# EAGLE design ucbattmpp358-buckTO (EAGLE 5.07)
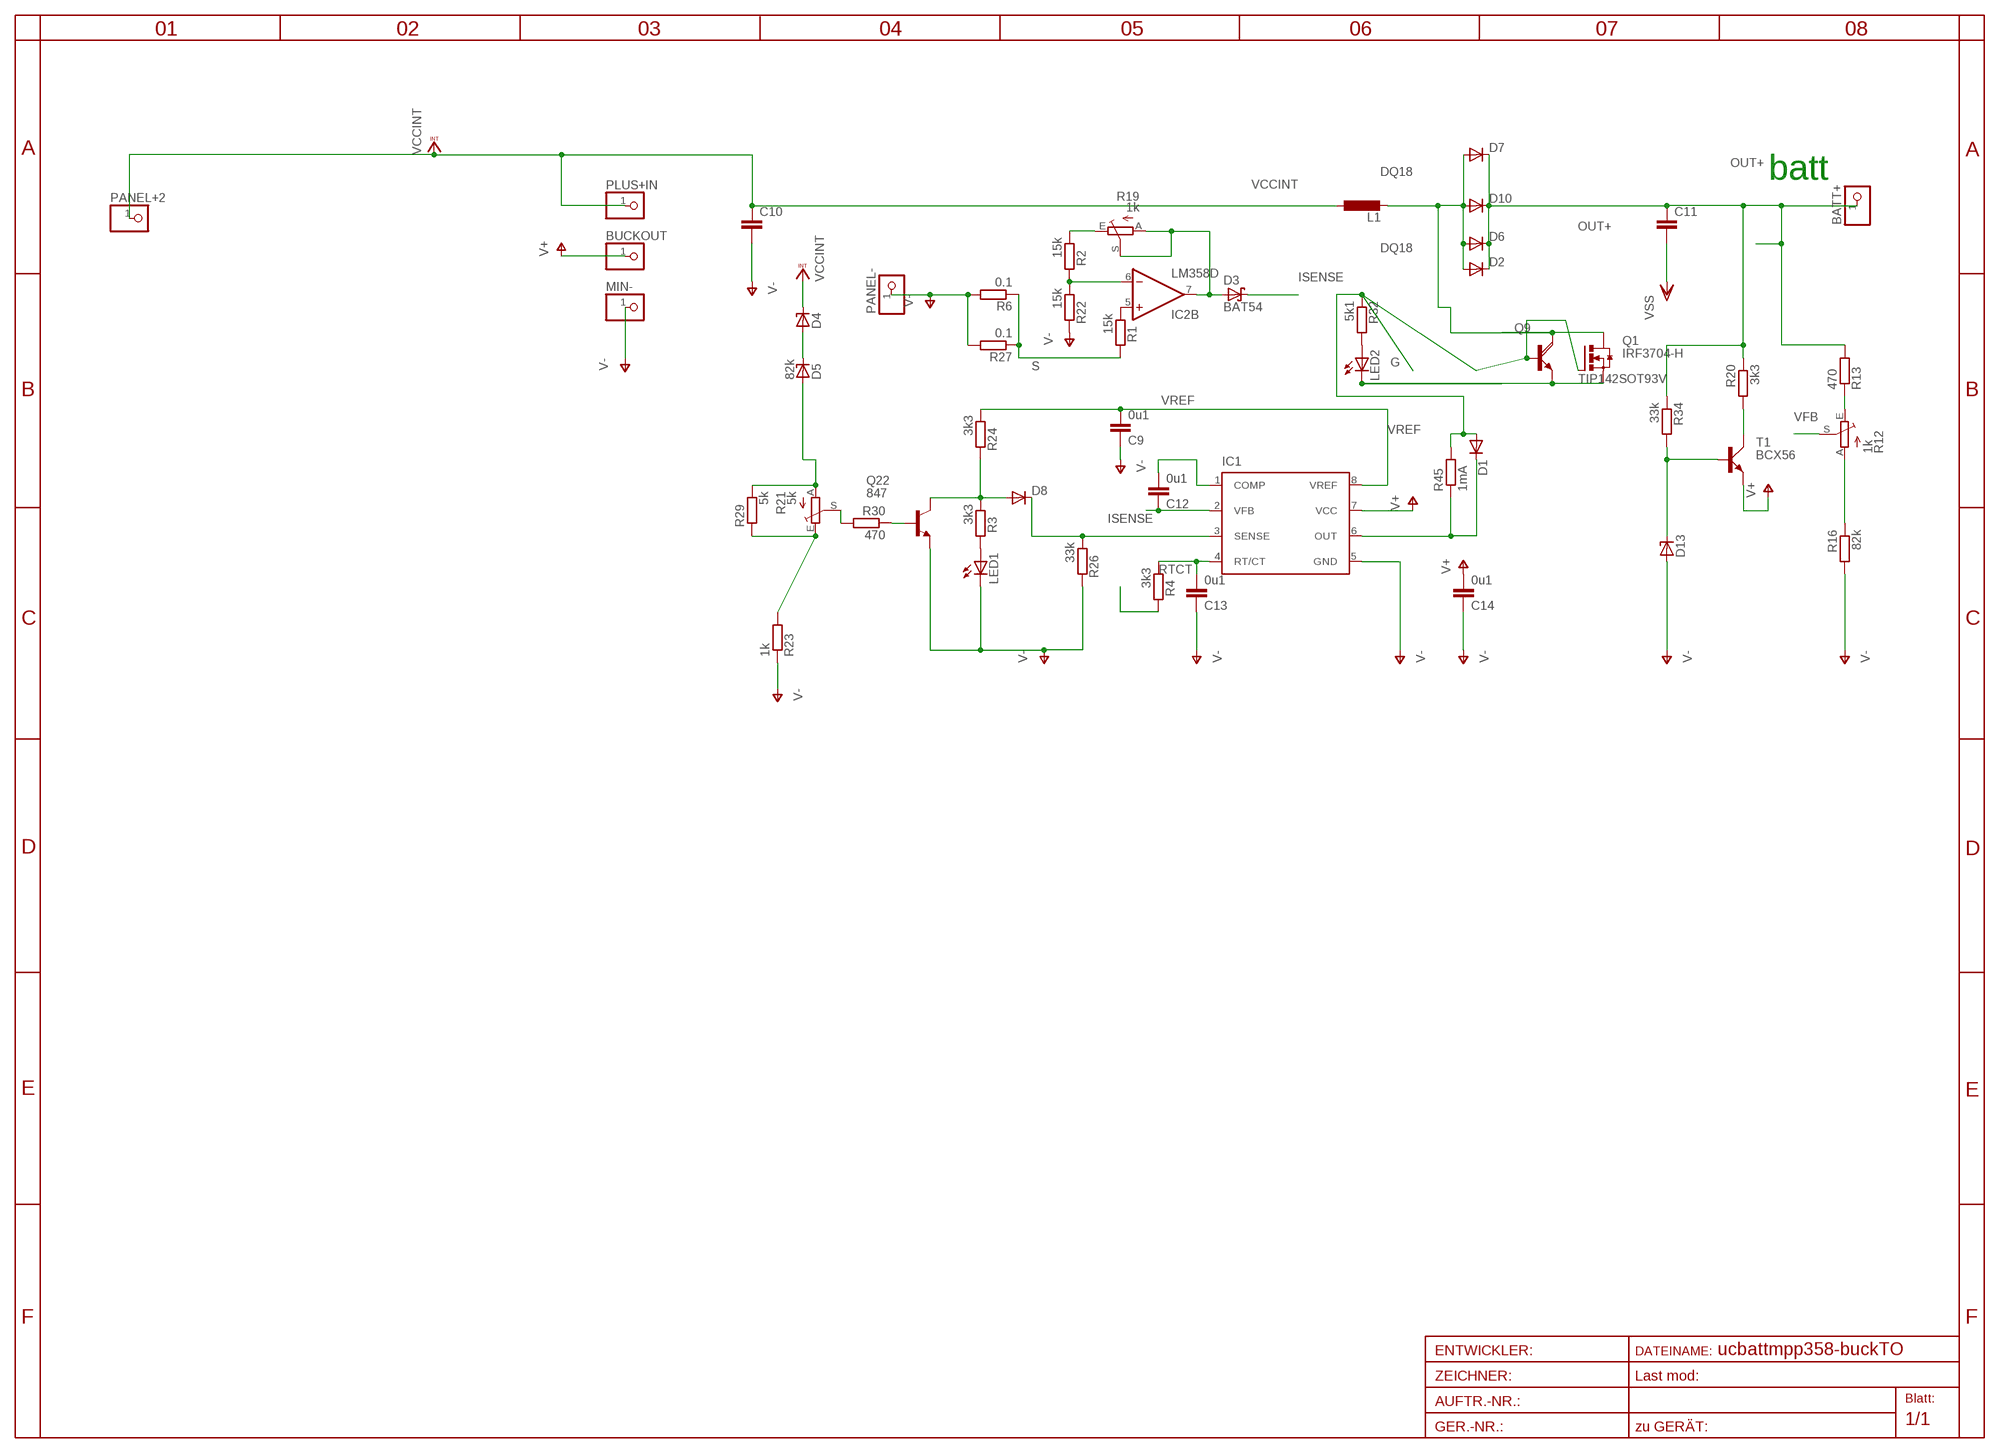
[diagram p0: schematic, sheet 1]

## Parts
BATT+  PINHD-1X12MM3  [1X2MM3]
BUCKOUT  PINHD-1X11MM0  [1X1MM0]
C9  0u1  C-EUC1206  [C1206]
C10  C-EU075-052X106  [C075-052X106]
C11  C-EU075-052X106  [C075-052X106]
C12  0u1  C-EUC0805  [C0805]
C13  0u1  C-EUC1206  [C1206]
C14  0u1  C-EUC1206  [C1206]
D1  DIODE-MINIMELF  [MINIMELF]
D2  DIODE-SMC  [SMC]
D3  BAT54  [SOT23]
D4  ZENER-DIODESOD80C  [SOD80C]
D5  82k  ZENER-DIODESOD80C  [SOD80C]
D6  DIODE-SMC  [SMC]
D7  DIODE-SMC  [SMC]
D8  DIODE-MINIMELF  [MINIMELF]
D10  DIODE-SMC  [SMC]
D13  ZENER-DIODESOD80C  [SOD80C]
IC1  UC1843D8  [SO-08]
IC2  LM358D  [SO08]
L1  L-EUOPEN6  [OPEN6_3]
LED1  LEDCHIPLED_1206  [CHIPLED_1206]
LED2  LEDCHIPLED_1206  [CHIPLED_1206]
MIN-  PINHD-1X11MM0  [1X1MM0]
PANEL+2  PINHD-1X12MM3  [1X2MM3]
PANEL-  PINHD-1X12MM3  [1X2MM3]
PLUS+IN  PINHD-1X11MM0  [1X1MM0]
Q1  IRF3704-H  [TO220BH]
Q9  TIP142SOT93V  [SOT93V]
Q22  847  BC847ASMD  [SOT23]
R1  15k  R-EU_R0805  [R0805]
R2  15k  R-EU_R0805  [R0805]
R3  3k3  R-EU_R0805  [R0805]
R4  3k3  R-EU_R0805  [R0805]
R6  0.1  R-EU_0207/10  [0207/10]
R12  1k  TRIM_EU-S64W  [S64W]
R13  470  R-EU_R0805  [R0805]
R16  82k  R-EU_R0805  [R0805]
R19  1k  TRIM_EU-S64W  [S64W]
R20  3k3  R-EU_R0805  [R0805]
R21  5k  TRIM_EU-S64W  [S64W]
R22  15k  R-EU_R0805  [R0805]
R23  1k  R-EU_R0805  [R0805]
R24  3k3  R-EU_R0805  [R0805]
R26  33k  R-EU_R0805  [R0805]
R27  0.1  R-EU_R3216  [R3216]
R29  5k  R-EU_R0805  [R0805]
R30  470  R-EU_R0805  [R0805]
R32  5k1  R-EU_R0805  [R0805]
R34  33k  R-EU_R0805  [R0805]
R45  1mA  R-EU_R0805  [R0805]
T1  BCX56  [SOT223]

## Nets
DQ18: D2.A D6.A D7.A D10.A L1.2 Q1.D Q9.C
G: D1.A Q1.G Q9.B R32.1 R45.2
ISENSE: D3.3(C) D8.C IC1.3(SENSE) R26.1
N$1: IC2.5(B:+IN) R1.1
N$2: R2.1 R19.E
N$3: Q22.1(B) R30.1
N$4: LED1.A R3.2
N$5: LED2.A R32.2
N$18: C12.2 IC1.1(COMP)
N$21: R12.A R16.1
N$22: D3.1(A) IC2.7(B:OUT) R19.A R19.S
N$23: R20.2 T1.2(C)
N$25: D1.C IC1.6(OUT) R45.1
N$26: D13.C R34.2 T1.1(B)
N$27: IC2.6(B:-IN) R2.2 R22.1
N$30: D4.A D5.C
N$32: D5.A R21.A R29.1
N$34: R21.E R23.2 R29.2
N$37: R12.E R13.1
N$71: D8.A Q22.3(C) R3.1 R24.2
OUT+: BATT+.1 C11.1 D2.C D6.C D7.C D10.C R13.2 R20.1 R34.1
PRB1: R21.S R30.2
RTCT: C13.2 IC1.4(RT/CT) R4.1
S: LED2.C Q1.S Q9.E R1.2 R6.1 R27.1
V+: BUCKOUT.1 C14.2 IC1.7(VCC) T1.3(E)
V-: C9.1 C10.2 C11.2 C13.1 C14.1 D13.A IC1.5(GND) LED1.C MIN-.1 PANEL-.1 Q22.2(E) R6.2 R16.2 R22.2 R23.1 R26.2 R27.2 ; supply symbol labelled VSS
VCCINT: C10.1 D4.C L1.1 PANEL+2.1 PLUS+IN.1
VFB: C12.1 IC1.2(VFB) R12.S
VREF: C9.2 IC1.8(VREF) R4.2 R24.1
Unconnected: IC2.1(A:OUT) IC2.2(A:-IN) IC2.3(A:+IN)

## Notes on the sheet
- batt

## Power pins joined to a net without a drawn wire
V+: IC2.8(P:V+)
V-: IC2.4(P:V-)

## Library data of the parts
BATT+ BUCKOUT MIN- PANEL+2 PANEL- PLUS+IN = pinhead:PINHD-1X1: PIN HEADER
C9-C14 = rcl:C-EU: CAPACITOR, European symbol
D1 D2 D6-D8 D10 = diode:DIODE-: DIODE
D3 = diode:BAT54: Schottky Diodes
D4 D5 D13 = diode:ZENER-DIODE: Z-Diode
IC1 = texas:UC1843D8: PULSE WIDTH MODULATOR
IC2 = linear:LM358: OP AMP also LM158; LM258; LM2904 Source: http://cache.national.com/ds/LM/LM158.pdf
L1 = rcl:L-EU: INDUCTOR, European symbol
LED1 LED2 = led:LED: LED
Q1 = transistor-power:IRF3704: SMPS MOSFET HEXFET® Power MOSFET Source: http://www.irf.com/product-info/datasheets/data/irf3704.pdf
Q9 = transistor-power:TIP142: NPN DARLINGTON TRANSISTOR
Q22 = transistor-npn:BC847*: NPN Transistor
R1-R4 R6 R13 R16 R20 R22-R24 R26 R27 R29 R30 R34 = rcl:R-EU_: RESISTOR, European symbol
R12 R19 R21 = pot:TRIM_EU-: POTENTIOMETER
R32 R45 = rcl-2:R-EU_: RESISTOR, European symbol
T1 = transistor-power:BCX56

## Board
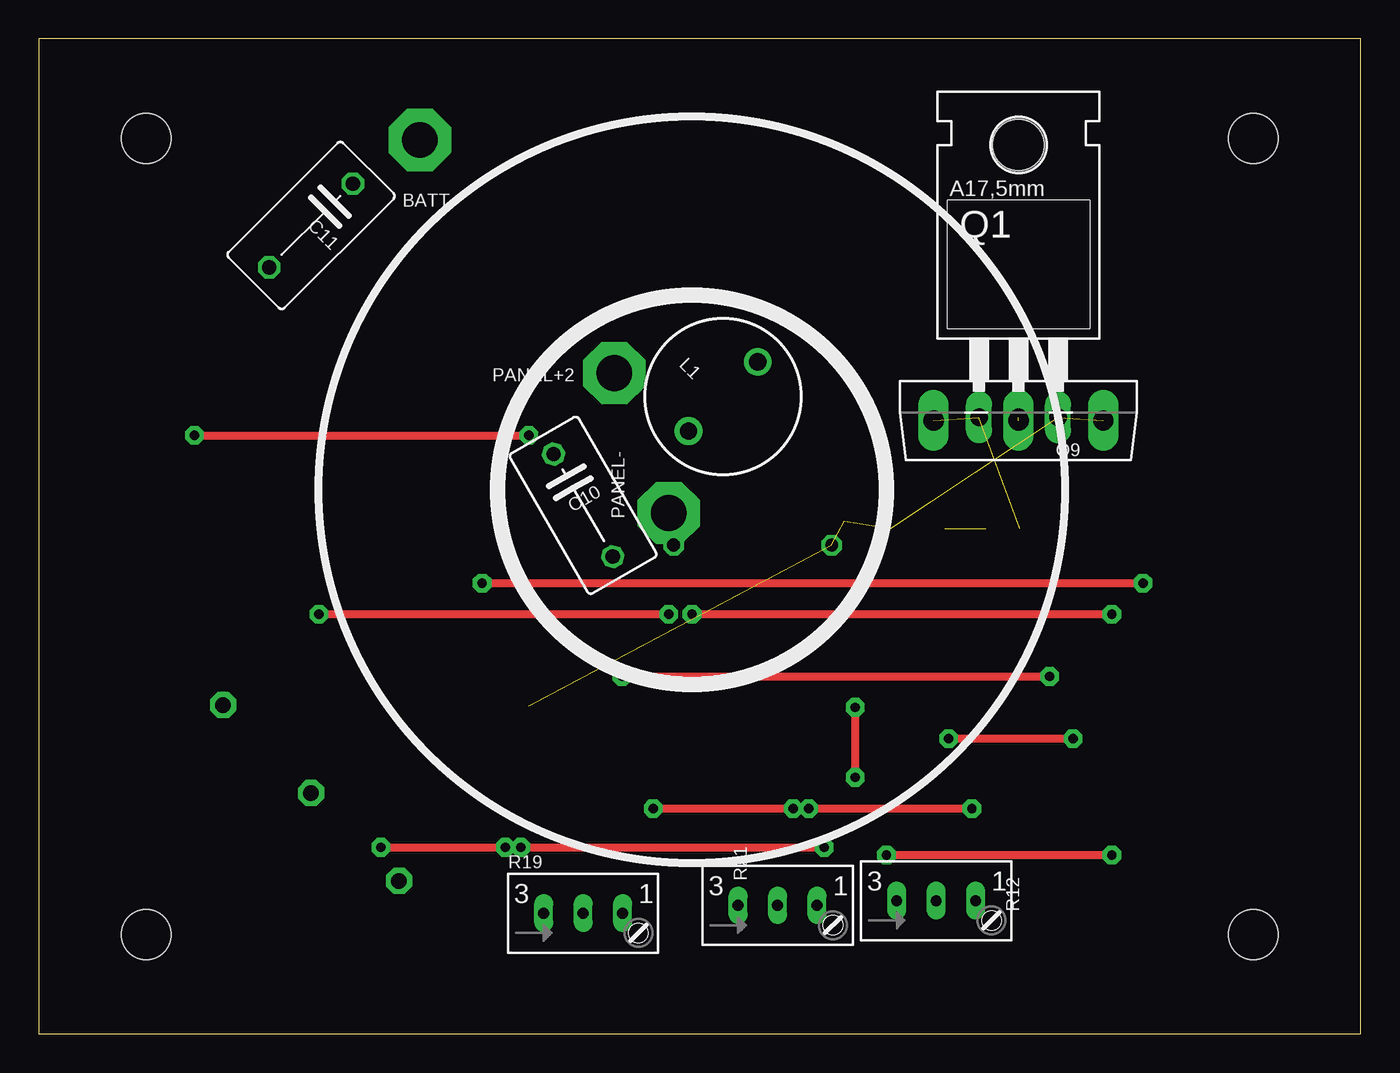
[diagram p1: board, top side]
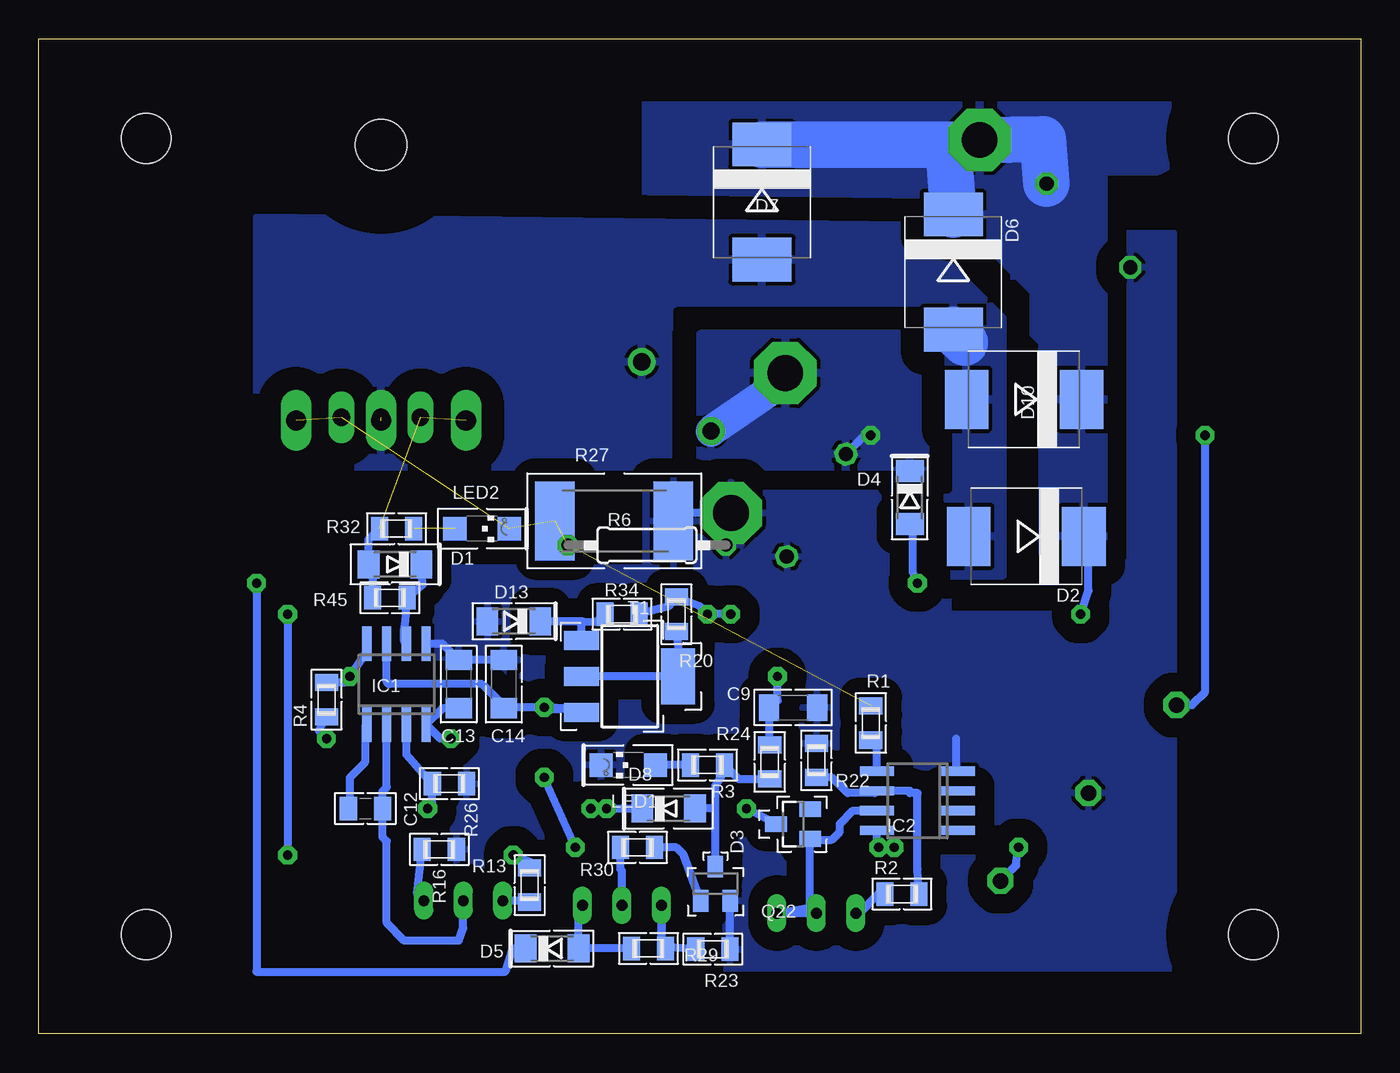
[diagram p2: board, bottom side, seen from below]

Size 85 x 64 mm. Coordinates in mm from the lower left corner, seen from the top.
Outline: 0,0 85,0 85,64 0,64 0,0
Copper layers (1*16): Top 0.035mm / dielectric 1.5mm / Bottom 0.035mm
Design rules "default *": minimum track width 10mil, minimum drill 24mil, track to track 8mil, track to pad 8mil, pad to pad 8mil, via to via 8mil, smd to smd 8mil, copper to edge 4mm, drill to drill 8mil, minimum pad ring 10mil, minimum via ring 8mil, stop-mask expansion 4mil, vias tented up to drill 0mil, thermal gap 10mil
Holes 3.2 mm at 6.9,57.6 6.9,6.4 78.1,6.4 78.1,57.6

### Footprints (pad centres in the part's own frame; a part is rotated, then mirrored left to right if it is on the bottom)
1X2MM3 = drill 2.3 pad 4 octagon: 1 0,0
1X1MM0 = drill 1 pad 1.676 octagon: 1 0,0
C1206 = smd 1.3 x 1.7: 1 -1.55,0; 2 1.55,0
C075-052X106 = drill 0.914 octagon: 1 -3.81,0; 2 3.81,0
C0805 = smd 1.1 x 1.5: 1 -1.1,0; 2 1.1,0
MINIMELF = smd 1.4 x 1.8: A 1.7,0; C -1.7,0
SMC = smd 2.8 x 3.8: A 3.7,0; C -3.7,0
SOT23 = smd 1 x 1.4: 1 -0.95,-1.1; 2 0.95,-1.1; 3 0,1.1
SOD80C = smd 1.4 x 1.8: A 1.7,0; C -1.7,0
SO-08 = smd 0.6 x 2.2: 1 -1.905,-2.6; 2 -0.635,-2.6; 3 0.635,-2.6; 4 1.905,-2.6; 5 1.905,2.6; 6 0.635,2.6; 7 -0.635,2.6; 8 -1.905,2.6
SO08 = smd 0.6 x 2.2: 1 -1.905,-2.6; 2 -0.635,-2.6; 3 0.635,-2.6; 4 1.905,-2.6; 5 1.905,2.6; 6 0.635,2.6; 7 -0.635,2.6; 8 -1.905,2.6
OPEN6_3 = drill 1.1 pad 1.778 round: 1 -3.15,0; 2 3.15,0
CHIPLED_1206 = smd 1.5 x 1.5: A 0,-1.75; C 0,1.75
TO220BH = drill 1.118 long: D 0,-6.35; G -2.54,-6.35; S 2.54,-6.35 | hole 3.302: 0,11.176
SOT93V = drill 1.3 pad 1.676 long: B -5.461,-2.54; C 0,-2.54; E 5.461,-2.54
R0805 = smd 1.1 x 1.5: 1 -1.1,0; 2 1.1,0
0207/10 = drill 0.813 octagon: 1 -5.08,0; 2 5.08,0
S64W = drill 0.7 long: A 2.54,1.27; E -2.54,1.27; S 0,1.27
R3216 = smd 2.54 x 5.08: 1 -3.81,0; 2 3.81,0
SOT223 = smd 1.219 x 2.235: 1 -2.311,-3.099; 2 0,-3.099; 3 2.311,-3.099 | smd 3.6 x 2.2: 4 0,3.099

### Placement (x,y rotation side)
BATT+  24.5,57.5 0 top
BUCKOUT  23.16,9.84 90 top
C9  36.5,21 180 bottom
C10  35,34 300 top
C11  17.5,52 225 top
C12  64,14.5 180 bottom
C13  58,22.5 270 bottom
C14  55.1,22.5 270 bottom
D1  62.1,30.2 180 bottom
D2  21.5,32 180 bottom
D3  36.5,13.5 90 bottom
D4  29,34.5 270 bottom
D5  52,5.5 0 bottom
D6  26.2,49 270 bottom
D7  38.5,53.5 270 bottom
D8  44.5,14.5 0 bottom
D10  21.65,40.81 180 bottom
D13  54.46,26.55 180 bottom
IC1  62,22.5 0 bottom
IC2  28.5,15 90 bottom
L1  44,41 45 top
LED1  47.1,17.3 90 bottom
LED2  56.5,32.5 270 bottom
MIN-  17.5,15.5 315.7 top
PANEL+2  37,42.5 0 top
PANEL-  40.5,33.5 90 top
PLUS+IN  11.84,21.16 90 top
Q1  63,46 0 top
Q9  63,42 0 top
Q22  41.49,9.66 0 bottom
R1  31.5,20 90 bottom
R2  29.5,9 0 bottom
R3  42,17.3 180 bottom
R4  66.5,21.5 90 bottom
R6  45.9,31.45 0 bottom
R12  57.7,7.3 0 top
R13  53.44,9.58 90 bottom
R16  59.25,11.88 0 bottom
R19  35,6.5 0 top
R20  44,27 270 bottom
R21  47.51,7 0 top
R22  35,17.6 90 bottom
R23  41.66,5.46 180 bottom
R24  38,17.5 270 bottom
R26  58.6,16.1 0 bottom
R27  48,33 0 bottom
R29  45.8,5.5 0 bottom
R30  46.5,12 180 bottom
R32  62,32.5 0 bottom
R34  47.5,27 180 bottom
R45  62.43,28.05 180 bottom
T1  47,23 270 bottom

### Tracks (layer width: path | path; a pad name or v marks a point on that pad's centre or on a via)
DQ18  (1 unrouted)
  Bottom 3: D6.A 25.8,44.8 25.45,44.45
  pour Bottom (isolate 1.5, rank 2): 29,52 71,52.5 71,36.5 44.5,36.5 44.5,45.5 27.5,45.5 27.5,29.5 23,29.5 23,46
G  (2 unrouted)
  Bottom 0.5: R45.2 63.53,29.43 D1.A 63.8,31.8 R32.1
ISENSE  (via drill 0.6 pad 1.2)
  Top 0.5: v49.5,14.5 v60,14.5 | v39.5,14.5 v48.5,14.5
  Bottom 0.5: IC1.3 61.37,17.96 R26.1 59.7,14.8 v60,14.5 | v49.5,14.5 v48.5,14.5 D8.C | D3.3 v39.5,14.5
N$1
  Bottom 0.5: IC2.5 31.1,18.5 R1.1
N$2
  Bottom 0.5: R2.1 31,9 32.23,7.77 R19.E
N$3
  Bottom 0.5: Q22.1 43.56,11.56 44,12 R30.1
N$4
  Bottom 0.5: R3.2 LED1.A
N$5  (1 unrouted)
N$18
  Bottom 0.5: C12.2 65,14.6 65,16.5 64,17.5 64,19.8 IC1.1
N$21
  Bottom 0.5: R12.A 60.67,9.01 R16.1
N$22
  Bottom 0.5: IC2.7 32.63,14.37 33.5,13.5 33.5,13 34,12.5 35.35,12.5 D3.1 35.4,8.13 R19.A R19.S
N$23
  Bottom 0.5: T1.2 43.6,23 R20.2
N$25
  Bottom 0.5: IC1.6 61.5,25.23 61.5,26 61.43,26.57 R45.1 60.33,28.87 D1.C
N$26
  Bottom 0.5: R34.2 49.21,26.5 49.99,26.52 | 49.99,26.52 D13.C | T1.1 50.1,26.42 49.99,26.52
N$27
  Bottom 0.5: R2.2 28.5,10.6 28.5,15.5 29,15.5 29,15.63 IC2.6 31.23,15.5 33,15.5 34,16.5 R22.1
N$30  (via drill 0.6 pad 1.2)
  Top 0.5: v28.5,29 v71,29
  Bottom 0.5: D5.C 54.5,5.5 55,4 71,4 v71,29 | D4.A 28.8,32.5 28.8,29.7 v28.5,29
N$32
  Bottom 0.5: R29.1 D5.A 50.3,8.34 R21.A
N$34
  Bottom 0.5: R29.2 44.5,5.5 45,6 45,8.56 R21.E 44.9,5.59 R23.2
N$37
  Bottom 0.5: R13.1 53.03,8.57 R12.E
N$71
  Bottom 0.5: Q22.3 41.49,14.5 | 41.49,14.5 41.49,15.96 40.9,16.87 R3.1 40,16.4 R24.2 | 41.49,14.5 D8.A
OUT+  (via drill 0.6 pad 1.2)
  Top 0.5: v69,11.5 v54.5,11.5 | v18,27 v40.5,27 | v42,27 v69,27
  Bottom 0.5: R34.1 44.5,27.5 R20.1 42.5,27.5 v42,27 v40.5,27 | v69,27 v69,11.5 | v54.5,11.5 53.26,11 R13.2 | 17.5,32 17.5,28.5 v18,27
  Bottom 3: C11.1 20.44,57.56 BATT+.1 24.8,57.2 26.5,57.2 | 26.5,57.2 D7.C | 26.5,57.2 D6.C
  pour Bottom (isolate 1.5, rank 3): 12,56 12,60.5 46,60.5 46,53.5 29.5,53.5 20.5,44.5 20.5,31 20,30.5 16.5,30.5 16.5,55.5 13,55.5
PRB1
  Bottom 0.5: R30.2 47.6,10.6 47.5,10.5 47.5,8.6 R21.S
RTCT  (via drill 0.6 pad 1.2)
  Top 0.5: v58.5,19 v66.5,19
  Bottom 0.5: C13.2 59.05,20.95 IC1.4 59.2,19 v58.5,19 | v66.5,19 67,19.5 R4.1
S  (5 unrouted)
V+  (via drill 0.6 pad 1.2)
  Top 0.5: v31,12 v50.5,12 | v52.5,16.5 v52.5,21 | v22,12 v30,12
  Bottom 0.5: IC2.8 31.1,12.1 v31,12 v30,12 | v50.5,12 v52.5,16.5 | IC1.7 62.63,22.64 62.5,22.5 56.5,22.5 55,21 | 55,21 52.41,21 50.94,20.94 | 50.94,20.94 T1.3 | v52.5,21 52,20.88 50.94,20.94 | BUCKOUT.1 22.16,10.84 v22,12 | C14.2 55.05,21 55,21
V-
  Bottom 0.5: C14.1 C13.1 59.05,25.1 IC1.5 | R23.1 40.54,8.47 Q22.2 | IC2.4 26,17 26,19 | R27.2 43.69,33.5 PANEL-.1
  pour Bottom (isolate 1.25, rank 4): 68.5,1 12,1.5 12,51.5 17,51.5 16.5,27 26.5,27 26.5,35.5 46,36 46,30 66.5,30
VCCINT  (via drill 0.6 pad 1.2)
  Top 0.5: v10,38.5 v31.5,38.5
  Bottom 0.5: PLUS+IN.1 10.84,21.16 10,22 v10,38.5 | v31.5,38.5 31.89,38.5 C10.1
  Bottom 2: 37,42.05 L1.1
  Bottom 3: PANEL+2.1 37,42.05
  pour Bottom (isolate 1.5): 28,45 42.5,45 42.5,36.5 28,36.5
VFB
  Bottom 0.5: IC1.2 62.63,15.87 62.9,15.6 C12.1 62.9,12.66 62.63,12.4 62.63,7.13 61.5,6 58,6 57.7,6.79 R12.S
VREF  (via drill 0.6 pad 1.2)
  Top 0.5: v37.5,23 v65,23
  Bottom 0.5: R24.1 C9.2 37.5,21.45 v37.5,23 | IC1.8 63.91,24.59 v65,23 65.4,22.6 R4.2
